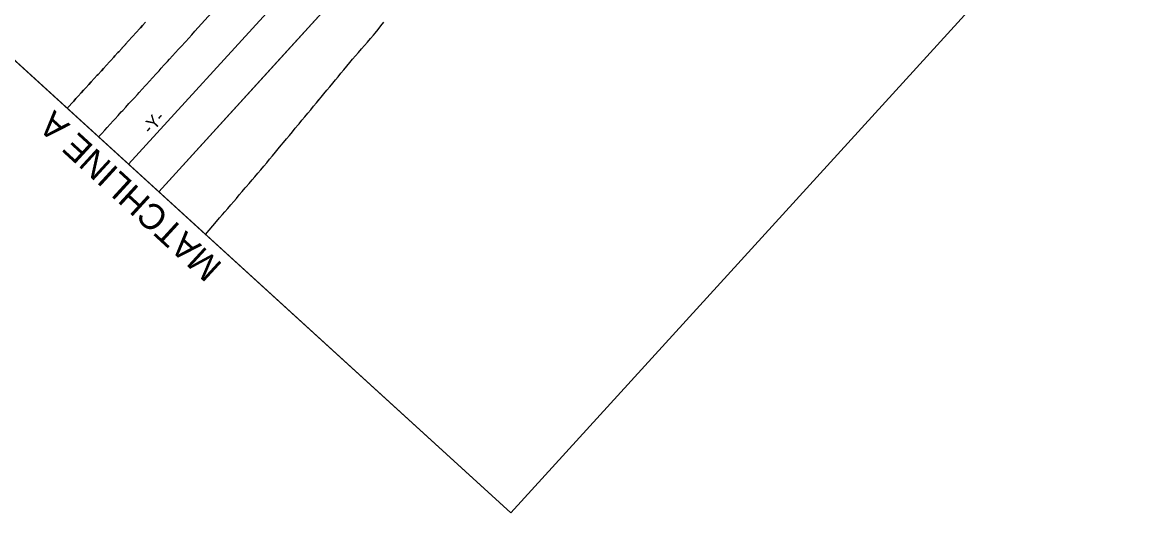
# Model space of a CAD drawing. Extents: x 1807040 to 1808827, y 913493 to 915218.
# Drawn here: x 1807609 to 1808221, y 913493 to 913762 of the extents above; entities that cross this region are included whole.
import ezdxf

# ---------------------------------------------------------------- set-up
doc = ezdxf.new("R2010")
doc.units = 0
for name, color, linetype in [('Matchline Text', 7, 'Continuous'), ('Old_Level_14', 7, 'Continuous'), ('Prop EOT', 7, 'Continuous'), ('Prop Horizontal Alignment Direction Label', 7, 'Continuous'), ('Scratch_Level_0', 7, 'Continuous'), ('Scratch_Level_1', 7, 'Continuous'), ('Scratch_Level_3', 7, 'Continuous')]:
    doc.layers.add(name, color=color, linetype=linetype)

msp = doc.modelspace()

# ---------------------------------------------------------------- linework, layer by layer
at = {"layer": 'Old_Level_14'}
msp.add_line((1807489.01, 913846.57), (1807877.03, 913492.93), dxfattribs=at)
at = {"layer": 'Prop EOT'}
msp.add_line((1807683.94, 913668.92), (1807845.7, 913846.32), dxfattribs=at)
for points in [[(1807651, 913698.94), (1807652.73, 913700.86), (1807654.4, 913702.72), (1807655.64, 913704.08), (1807657.32, 913705.94), (1807658.99, 913707.79), (1807660.01, 913708.91), (1807661.71, 913710.76), (1807663.4, 913712.6), (1807664.22, 913713.49), (1807665.91, 913715.34), (1807667.6, 913717.18), (1807668.89, 913718.59), (1807670.59, 913720.42), (1807672.28, 913722.26), (1807673.16, 913723.2), (1807674.84, 913725.05), (1807676.52, 913726.9), (1807677.23, 913727.68), (1807678.9, 913729.54), (1807680.57, 913731.41), (1807680.71, 913731.57), (1807682.41, 913733.4), (1807684.11, 913735.24), (1807685.33, 913736.56), (1807687.02, 913738.41), (1807688.7, 913740.26), (1807689.83, 913741.51), (1807691.51, 913743.36), (1807693.2, 913745.21), (1807694.88, 913747.05), (1807696.56, 913748.9), (1807698.24, 913750.75), (1807698.73, 913751.29), (1807700.41, 913753.14), (1807702.09, 913754.99), (1807703.77, 913756.85), (1807761.01, 913819.97)], [(1807633.78, 913714.63), (1807637.38, 913718.6), (1807638.61, 913719.95), (1807639.82, 913721.28), (1807641.51, 913723.12), (1807642.77, 913724.5), (1807643.98, 913725.84), (1807645.67, 913727.69), (1807646.91, 913729.05), (1807648.6, 913730.9), (1807650.28, 913732.75), (1807650.69, 913733.2), (1807652.38, 913735.04), (1807652.54, 913735.22), (1807653.65, 913736.43), (1807655.33, 913738.3), (1807657.02, 913740.15), (1807657.64, 913740.83), (1807659.31, 913742.69), (1807659.93, 913743.37), (1807661.62, 913745.21), (1807662.01, 913745.63), (1807663.69, 913747.48), (1807663.98, 913747.79), (1807665.66, 913749.64), (1807665.75, 913749.74), (1807667.41, 913751.61), (1807667.59, 913751.81), (1807669.28, 913753.65), (1807669.82, 913754.22), (1807671.49, 913756.08), (1807671.74, 913756.36), (1807673.43, 913758.21), (1807673.93, 913758.76), (1807675.11, 913760.08), (1807676.79, 913761.93)], [(1807709.63, 913645.5), (1807715.72, 913652.61), (1807717.36, 913654.5), (1807718.99, 913656.39), (1807720.27, 913657.87), (1807721.89, 913659.78), (1807723.5, 913661.69), (1807725.11, 913663.6), (1807726.51, 913665.25), (1807728.12, 913667.16), (1807729.74, 913669.07), (1807731.35, 913670.98), (1807731.86, 913671.58), (1807733.51, 913673.47), (1807735.15, 913675.35), (1807736.7, 913677.13), (1807738.32, 913679.03), (1807739.94, 913680.94), (1807741.54, 913682.82), (1807743.13, 913684.75), (1807744.73, 913686.68), (1807746.32, 913688.6), (1807747.91, 913690.53), (1807749.51, 913692.46), (1807751.1, 913694.38), (1807752.4, 913695.96), (1807754, 913697.88), (1807755.6, 913699.8), (1807757.2, 913701.72), (1807758.8, 913703.65), (1807760.4, 913705.57), (1807760.89, 913706.15), (1807762.49, 913708.07), (1807764.09, 913709.99), (1807765.69, 913711.91), (1807767.29, 913713.83), (1807768.89, 913715.75), (1807770.49, 913717.67), (1807772.09, 913719.6), (1807772.95, 913720.64), (1807774.55, 913722.56), (1807776.14, 913724.49), (1807777.73, 913726.42), (1807779.32, 913728.35), (1807780.91, 913730.27), (1807782.28, 913731.93), (1807783.86, 913733.86), (1807785.45, 913735.79), (1807787.04, 913737.72), (1807788.63, 913739.65), (1807790.17, 913741.52), (1807791.81, 913743.41), (1807793.44, 913745.3), (1807795.08, 913747.19), (1807796.72, 913749.08), (1807798.35, 913750.97), (1807799.99, 913752.86), (1807801.63, 913754.75), (1807802.63, 913755.9), (1807804.17, 913757.87), (1807805.72, 913759.83), (1807807.27, 913761.8)]]:
    msp.add_lwpolyline(points, dxfattribs=at)
at = {"layer": 'Scratch_Level_0'}
for p, q in [((1807808.33, 913805.34), (1807748.66, 913739.9)), ((1807748.66, 913739.9), (1807683.94, 913668.92)), ((1807633.78, 913714.63), (1807651, 913698.94)), ((1807683.94, 913668.92), (1807709.63, 913645.5))]:
    msp.add_line(p, q, dxfattribs=at)
for points in [[(1807651, 913698.94), (1807652.73, 913700.86), (1807654.4, 913702.72), (1807655.64, 913704.08), (1807657.32, 913705.94), (1807658.99, 913707.79), (1807660.01, 913708.91), (1807661.71, 913710.76), (1807663.4, 913712.6), (1807664.22, 913713.49), (1807665.91, 913715.34), (1807667.6, 913717.18), (1807668.89, 913718.59), (1807670.59, 913720.42), (1807672.28, 913722.26), (1807673.16, 913723.2), (1807674.84, 913725.05), (1807676.52, 913726.9), (1807677.23, 913727.68), (1807678.9, 913729.54), (1807680.57, 913731.41), (1807680.71, 913731.57), (1807682.41, 913733.4), (1807684.11, 913735.24), (1807685.33, 913736.56), (1807687.02, 913738.41), (1807688.7, 913740.26), (1807689.83, 913741.51), (1807691.51, 913743.36), (1807693.2, 913745.21), (1807694.88, 913747.05), (1807696.56, 913748.9), (1807698.24, 913750.75), (1807698.73, 913751.29), (1807700.41, 913753.14), (1807702.09, 913754.99), (1807703.77, 913756.85), (1807761.01, 913819.97)], [(1807676.79, 913761.93), (1807675.11, 913760.08), (1807673.93, 913758.76), (1807673.43, 913758.21), (1807671.74, 913756.36), (1807671.49, 913756.08), (1807669.82, 913754.22), (1807669.28, 913753.65), (1807667.59, 913751.81), (1807667.41, 913751.61), (1807665.75, 913749.74), (1807665.66, 913749.64), (1807663.98, 913747.79), (1807663.69, 913747.48), (1807662.01, 913745.63), (1807661.62, 913745.21), (1807659.93, 913743.37), (1807659.31, 913742.69), (1807657.64, 913740.83), (1807657.02, 913740.15), (1807655.33, 913738.3), (1807653.65, 913736.43), (1807652.54, 913735.22), (1807652.38, 913735.04), (1807650.69, 913733.2), (1807650.28, 913732.75), (1807648.6, 913730.9), (1807646.91, 913729.05), (1807645.67, 913727.69), (1807643.98, 913725.84), (1807642.77, 913724.5), (1807641.51, 913723.12), (1807639.82, 913721.28), (1807638.61, 913719.95), (1807637.38, 913718.6), (1807633.78, 913714.63)], [(1807771.59, 913719), (1807772.09, 913719.6), (1807772.95, 913720.64), (1807774.55, 913722.56), (1807776.14, 913724.49), (1807777.73, 913726.42), (1807779.32, 913728.35), (1807780.91, 913730.27), (1807782.28, 913731.93), (1807783.86, 913733.86), (1807785.45, 913735.79), (1807787.04, 913737.72), (1807788.63, 913739.65), (1807790.17, 913741.52), (1807791.81, 913743.41), (1807793.44, 913745.3), (1807795.08, 913747.19), (1807796.72, 913749.08), (1807798.35, 913750.97), (1807799.99, 913752.86), (1807801.63, 913754.75), (1807802.63, 913755.9), (1807804.17, 913757.87), (1807805.72, 913759.83), (1807807.27, 913761.8)], [(1807709.63, 913645.5), (1807715.72, 913652.61), (1807717.36, 913654.5), (1807718.99, 913656.39), (1807720.27, 913657.87), (1807721.89, 913659.78), (1807723.5, 913661.69), (1807725.11, 913663.6), (1807726.51, 913665.25), (1807728.12, 913667.16), (1807729.74, 913669.07), (1807731.35, 913670.98), (1807731.86, 913671.58), (1807733.51, 913673.47), (1807735.15, 913675.35), (1807736.7, 913677.13), (1807738.32, 913679.03), (1807739.94, 913680.94), (1807741.54, 913682.82), (1807743.13, 913684.75), (1807744.73, 913686.68), (1807746.32, 913688.6), (1807747.91, 913690.53), (1807749.51, 913692.46), (1807751.1, 913694.38), (1807752.4, 913695.96), (1807754, 913697.88), (1807755.6, 913699.8), (1807757.2, 913701.72), (1807758.8, 913703.65), (1807760.4, 913705.57), (1807760.89, 913706.15), (1807762.49, 913708.07), (1807764.09, 913709.99), (1807765.69, 913711.91), (1807767.29, 913713.83), (1807768.89, 913715.75), (1807770.49, 913717.67), (1807771.59, 913719)]]:
    msp.add_lwpolyline(points, dxfattribs=at)
at = {"layer": 'Scratch_Level_1'}
msp.add_lwpolyline([(1807489.01, 913846.57), (1807877.03, 913492.93), (1808826.79, 914534.98), (1808438.77, 914888.63)], close=True, dxfattribs=at)
at = {"layer": 'Scratch_Level_3'}
msp.add_line((1807667.44, 913683.95), (1808610.51, 914718.66), dxfattribs=at)

# ---------------------------------------------------------------- texts
at = {"layer": 'Matchline Text'}
msp.add_text('MATCHLINE A', height=14, rotation=137.47907, dxfattribs=at).set_placement((1807719.37, 913628.93))
at = {"layer": 'Prop Horizontal Alignment Direction Label'}
msp.add_text('-Y-', height=7, rotation=47.65322, dxfattribs=at).set_placement((1807679.34, 913700.05))

doc.saveas('drawing.dxf')
